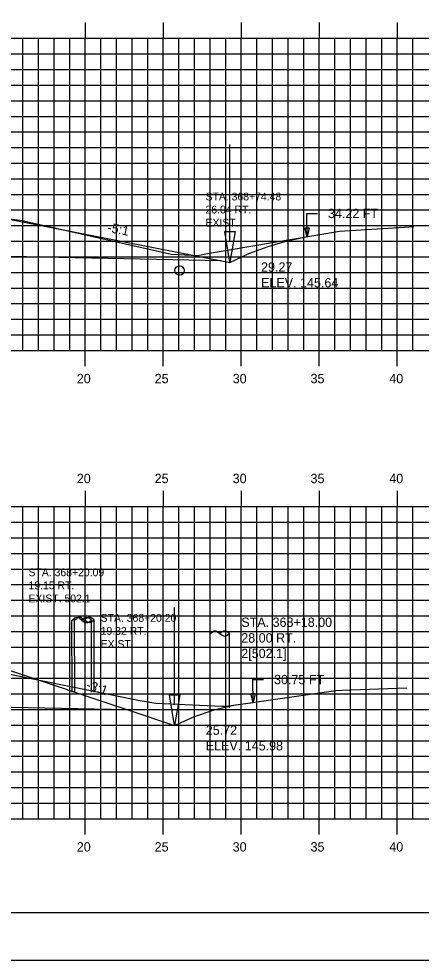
# Model space of a CAD drawing. Extents: x 1147855 to 1148025, y 608981 to 609091.
# Drawn here: x 1147953.9 to 1147979.7, y 608981.3 to 609041.6 of the extents above; entities that cross this region are included whole.
import ezdxf

# ---------------------------------------------------------------- set-up
doc = ezdxf.new("R2010")
doc.units = 0
for name, color, linetype in [('ANNOTATION', 7, 'Continuous'), ('BORDER', 7, 'Continuous'), ('D_Drainage_Ditch_Line', 7, 'Continuous'), ('D_Roadway_SlopeLines', 7, 'Continuous'), ('D_Roadway_SubGrade', 7, 'Continuous'), ('D_Text_Monospaced', 7, 'Continuous'), ('D_Text_Standard', 7, 'Continuous'), ('D_Utilities_Pole_Joint_Rt', 7, 'Continuous'), ('H_V ANNOTATION', 7, 'Continuous'), ('MAJOR', 7, 'Continuous'), ('MINOR', 7, 'Continuous'), ('PLOT BOUNDARY', 7, 'Continuous'), ('S_Drainage_Invert', 7, 'Continuous'), ('S_Roadway_Centerline', 7, 'Continuous'), ('S_Utilities_Pole_Power', 7, 'Continuous')]:
    doc.layers.add(name, color=color, linetype=linetype)

msp = doc.modelspace()

# ---------------------------------------------------------------- linework, layer by layer
for points in [[(1147923.21, 609028.779), (1147923.211, 609028.779), (1147927.211, 609028.939), (1147938.211, 609029.159), (1147949.211, 609028.939), (1147953.211, 609028.779), (1147966.938, 609026.085), (1147967.48, 609025.978), (1147968.704, 609026.54), (1147969.928, 609026.999), (1147971.152, 609027.357), (1147972.377, 609027.613)], [(1147922.727, 608999.809), (1147923.21, 608999.889), (1147923.211, 608999.889), (1147927.211, 609000.049), (1147938.211, 609000.269), (1147949.211, 609000.049), (1147953.211, 608999.889), (1147960.934, 608997.315), (1147963.934, 608996.315), (1147963.962, 608996.329), (1147965.212, 608996.889), (1147966.462, 608997.318), (1147967.712, 608997.616), (1147968.962, 608997.784)]]:
    msp.add_lwpolyline(points)
at = {"layer": 'BORDER'}
msp.add_lwpolyline([(1147863.211, 608984.335), (1148023.211, 608984.335), (1148023.211, 609089.335), (1147863.211, 609089.335)], close=True, dxfattribs=at)
at = {"layer": 'D_Drainage_Ditch_Line'}
for p, q in [((1147967.48, 609027.291), (1147967.48, 609033.534)), ((1147963.934, 608997.627), (1147963.934, 609003.871))]:
    msp.add_line(p, q, dxfattribs=at)
for points in [[(1147967.151, 609027.947), (1147967.808, 609027.947), (1147967.48, 609025.978)], [(1147963.606, 608998.283), (1147964.262, 608998.283), (1147963.934, 608996.315)]]:
    msp.add_lwpolyline(points, close=True, dxfattribs=at)
at = {"layer": 'D_Roadway_SlopeLines'}
for points in [[(1147967.48, 609025.978), (1147968.704, 609026.54), (1147969.928, 609026.999), (1147971.152, 609027.357), (1147972.377, 609027.613)], [(1147966.938, 609026.085), (1147967.48, 609025.978)], [(1147963.934, 608996.315), (1147963.962, 608996.329), (1147965.212, 608996.889), (1147966.462, 608997.318), (1147967.712, 608997.616), (1147968.962, 608997.784)], [(1147960.934, 608997.315), (1147963.934, 608996.315)]]:
    msp.add_lwpolyline(points, dxfattribs=at)
at = {"layer": 'D_Roadway_SubGrade'}
for points in [[(1147949.211, 609028.523), (1147949.211, 609028.689), (1147953.211, 609028.529), (1147953.211, 609028.779), (1147953.211, 609028.779), (1147966.938, 609026.085), (1147949.211, 609026.439)], [(1147949.211, 608999.633), (1147949.211, 608999.799), (1147953.211, 608999.639), (1147953.211, 608999.889), (1147953.211, 608999.889), (1147960.934, 608997.315), (1147949.211, 608997.549)]]:
    msp.add_lwpolyline(points, close=True, dxfattribs=at)
at = {"layer": 'D_Text_Standard'}
for points in [[(1147972.428, 609027.613), (1147972.408, 609029.117), (1147973.088, 609029.117)], [(1147968.962, 608997.784), (1147968.951, 608999.255), (1147969.631, 608999.255)]]:
    msp.add_lwpolyline(points, dxfattribs=at)
for points in [[(1147972.428, 609027.613), (1147972.275, 609028.193), (1147972.566, 609028.197)], [(1147968.962, 608997.784), (1147968.812, 608998.365), (1147969.103, 608998.367)]]:
    msp.add_lwpolyline(points, close=True, dxfattribs=at)
at = {"layer": 'D_Utilities_Pole_Joint_Rt'}
for p, q in [((1147966.211, 609002.199), (1147966.367, 609002.31)), ((1147966.211, 608997.442), (1147966.211, 609002.199)), ((1147966.679, 609002.31), (1147966.835, 609002.199)), ((1147966.991, 609002.31), (1147966.835, 609002.199)), ((1147966.835, 609002.199), (1147966.991, 609002.089)), ((1147967.461, 609002.199), (1147967.304, 609002.31)), ((1147967.304, 609002.089), (1147967.461, 609002.199)), ((1147967.461, 608997.442), (1147967.461, 609002.199))]:
    msp.add_line(p, q, dxfattribs=at)
for centre, start, end in [((1147966.523, 609002.089), 90, 125.26439), ((1147966.523, 609002.089), 54.73561, 90), ((1147967.148, 609002.089), 90, 125.26439), ((1147967.148, 609002.31), 234.73561, 270), ((1147967.148, 609002.089), 54.73561, 90), ((1147967.148, 609002.31), 270, 305.26439)]:
    msp.add_arc(centre, 0.271, start, end, dxfattribs=at)
at = {"layer": 'MAJOR'}
for p, q in [((1147958.211, 609041.337), (1147958.211, 609040.335)), ((1147963.211, 609041.337), (1147963.211, 609040.335)), ((1147968.211, 609041.337), (1147968.211, 609040.335)), ((1147973.211, 609041.337), (1147973.211, 609040.335)), ((1147978.211, 609041.337), (1147978.211, 609040.335)), ((1147868.211, 609040.335), (1148008.211, 609040.335)), ((1147868.211, 609040.335), (1148008.211, 609040.335)), ((1147958.211, 609020.335), (1147958.211, 609040.335)), ((1147963.211, 609020.335), (1147963.211, 609040.335)), ((1147968.211, 609020.335), (1147968.211, 609040.335)), ((1147973.211, 609020.335), (1147973.211, 609040.335)), ((1147978.211, 609020.335), (1147978.211, 609040.335)), ((1147868.211, 609035.335), (1148008.211, 609035.335)), ((1147868.211, 609030.335), (1148008.211, 609030.335)), ((1147868.211, 609025.335), (1148008.211, 609025.335)), ((1147868.211, 609020.335), (1148008.211, 609020.335)), ((1147868.211, 609020.335), (1148008.211, 609020.335)), ((1147958.211, 609019.333), (1147958.211, 609020.335)), ((1147963.211, 609019.333), (1147963.211, 609020.335)), ((1147968.211, 609019.333), (1147968.211, 609020.335)), ((1147973.211, 609019.333), (1147973.211, 609020.335)), ((1147978.211, 609019.333), (1147978.211, 609020.335)), ((1147958.211, 609011.337), (1147958.211, 609010.335)), ((1147963.211, 609011.337), (1147963.211, 609010.335)), ((1147968.211, 609011.337), (1147968.211, 609010.335)), ((1147973.211, 609011.337), (1147973.211, 609010.335)), ((1147978.211, 609011.337), (1147978.211, 609010.335)), ((1147868.211, 609010.335), (1148008.211, 609010.335)), ((1147868.211, 609010.335), (1148008.211, 609010.335)), ((1147958.211, 608990.335), (1147958.211, 609010.335)), ((1147963.211, 608990.335), (1147963.211, 609010.335)), ((1147968.211, 608990.335), (1147968.211, 609010.335)), ((1147973.211, 608990.335), (1147973.211, 609010.335)), ((1147978.211, 608990.335), (1147978.211, 609010.335)), ((1147868.211, 609005.335), (1148008.211, 609005.335)), ((1147868.211, 609000.335), (1148008.211, 609000.335)), ((1147868.211, 608995.335), (1148008.211, 608995.335)), ((1147868.211, 608990.335), (1148008.211, 608990.335)), ((1147868.211, 608990.335), (1148008.211, 608990.335)), ((1147958.211, 608989.333), (1147958.211, 608990.335)), ((1147963.211, 608989.333), (1147963.211, 608990.335)), ((1147968.211, 608989.333), (1147968.211, 608990.335)), ((1147973.211, 608989.333), (1147973.211, 608990.335)), ((1147978.211, 608989.333), (1147978.211, 608990.335))]:
    msp.add_line(p, q, dxfattribs=at)
at = {"layer": 'MINOR'}
for p, q in [((1147954.211, 609020.335), (1147954.211, 609040.335)), ((1147955.211, 609020.335), (1147955.211, 609040.335)), ((1147956.211, 609020.335), (1147956.211, 609040.335)), ((1147957.211, 609020.335), (1147957.211, 609040.335)), ((1147959.211, 609020.335), (1147959.211, 609040.335)), ((1147960.211, 609020.335), (1147960.211, 609040.335)), ((1147961.211, 609020.335), (1147961.211, 609040.335)), ((1147962.211, 609020.335), (1147962.211, 609040.335)), ((1147964.211, 609020.335), (1147964.211, 609040.335)), ((1147965.211, 609020.335), (1147965.211, 609040.335)), ((1147966.211, 609020.335), (1147966.211, 609040.335)), ((1147967.211, 609020.335), (1147967.211, 609040.335)), ((1147969.211, 609020.335), (1147969.211, 609040.335)), ((1147970.211, 609020.335), (1147970.211, 609040.335)), ((1147971.211, 609020.335), (1147971.211, 609040.335)), ((1147972.211, 609020.335), (1147972.211, 609040.335)), ((1147974.211, 609020.335), (1147974.211, 609040.335)), ((1147975.211, 609020.335), (1147975.211, 609040.335)), ((1147976.211, 609020.335), (1147976.211, 609040.335)), ((1147977.211, 609020.335), (1147977.211, 609040.335)), ((1147979.211, 609020.335), (1147979.211, 609040.335)), ((1147868.211, 609039.335), (1148008.211, 609039.335)), ((1147868.211, 609038.335), (1148008.211, 609038.335)), ((1147868.211, 609037.335), (1148008.211, 609037.335)), ((1147868.211, 609036.335), (1148008.211, 609036.335)), ((1147868.211, 609034.335), (1148008.211, 609034.335)), ((1147868.211, 609033.335), (1148008.211, 609033.335)), ((1147868.211, 609032.335), (1148008.211, 609032.335)), ((1147868.211, 609031.335), (1148008.211, 609031.335)), ((1147868.211, 609029.335), (1148008.211, 609029.335)), ((1147868.211, 609028.335), (1148008.211, 609028.335)), ((1147868.211, 609027.335), (1148008.211, 609027.335)), ((1147868.211, 609026.335), (1148008.211, 609026.335)), ((1147868.211, 609024.335), (1148008.211, 609024.335)), ((1147868.211, 609023.335), (1148008.211, 609023.335)), ((1147868.211, 609022.335), (1148008.211, 609022.335)), ((1147868.211, 609021.335), (1148008.211, 609021.335)), ((1147954.211, 608990.335), (1147954.211, 609010.335)), ((1147955.211, 608990.335), (1147955.211, 609010.335)), ((1147956.211, 608990.335), (1147956.211, 609010.335)), ((1147957.211, 608990.335), (1147957.211, 609010.335)), ((1147959.211, 608990.335), (1147959.211, 609010.335)), ((1147960.211, 608990.335), (1147960.211, 609010.335)), ((1147961.211, 608990.335), (1147961.211, 609010.335)), ((1147962.211, 608990.335), (1147962.211, 609010.335)), ((1147964.211, 608990.335), (1147964.211, 609010.335)), ((1147965.211, 608990.335), (1147965.211, 609010.335)), ((1147966.211, 608990.335), (1147966.211, 609010.335)), ((1147967.211, 608990.335), (1147967.211, 609010.335)), ((1147969.211, 608990.335), (1147969.211, 609010.335)), ((1147970.211, 608990.335), (1147970.211, 609010.335)), ((1147971.211, 608990.335), (1147971.211, 609010.335)), ((1147972.211, 608990.335), (1147972.211, 609010.335)), ((1147974.211, 608990.335), (1147974.211, 609010.335)), ((1147975.211, 608990.335), (1147975.211, 609010.335)), ((1147976.211, 608990.335), (1147976.211, 609010.335)), ((1147977.211, 608990.335), (1147977.211, 609010.335)), ((1147979.211, 608990.335), (1147979.211, 609010.335)), ((1147868.211, 609009.335), (1148008.211, 609009.335)), ((1147868.211, 609008.335), (1148008.211, 609008.335)), ((1147868.211, 609007.335), (1148008.211, 609007.335)), ((1147868.211, 609006.335), (1148008.211, 609006.335)), ((1147868.211, 609004.335), (1148008.211, 609004.335)), ((1147868.211, 609003.335), (1148008.211, 609003.335)), ((1147868.211, 609002.335), (1148008.211, 609002.335)), ((1147868.211, 609001.335), (1148008.211, 609001.335)), ((1147868.211, 608999.335), (1148008.211, 608999.335)), ((1147868.211, 608998.335), (1148008.211, 608998.335)), ((1147868.211, 608997.335), (1148008.211, 608997.335)), ((1147868.211, 608996.335), (1148008.211, 608996.335)), ((1147868.211, 608994.335), (1148008.211, 608994.335)), ((1147868.211, 608993.335), (1148008.211, 608993.335)), ((1147868.211, 608992.335), (1148008.211, 608992.335)), ((1147868.211, 608991.335), (1148008.211, 608991.335))]:
    msp.add_line(p, q, dxfattribs=at)
at = {"layer": 'PLOT BOUNDARY'}
msp.add_lwpolyline([(1147855.117, 608981.276), (1148025.117, 608981.276), (1148025.117, 609091.276), (1147855.117, 609091.276)], close=True, dxfattribs=at)
at = {"layer": 'S_Drainage_Invert'}
msp.add_circle((1147964.252, 609025.45), 0.3, dxfattribs=at)
at = {"layer": 'S_Roadway_Centerline'}
for points in [[(1147905.033, 609030.646), (1147917.167, 609029.936), (1147920.074, 609028.979), (1147920.713, 609028.933), (1147923.925, 609029.216), (1147924.199, 609029.231), (1147926.359, 609029.359), (1147926.651, 609029.377), (1147927.806, 609029.391), (1147938.591, 609029.489), (1147940.789, 609029.431), (1147952.444, 609028.899), (1147954.159, 609028.669), (1147954.197, 609028.662), (1147954.21, 609028.663), (1147954.245, 609028.651), (1147963.64, 609026.518), (1147963.717, 609026.515), (1147965.429, 609026.412), (1147966.055, 609026.554), (1147974.498, 609027.968), (1147978.677, 609028.23), (1147979.275, 609028.271)], [(1147903.402, 609000.314), (1147911.816, 609000.149), (1147915.16, 609000.018), (1147918.794, 608999.761), (1147922.073, 608999.773), (1147923.723, 608999.863), (1147925.309, 608999.916), (1147926.955, 609000.021), (1147933.547, 609000.1), (1147938.607, 609000.171), (1147945.257, 608999.995), (1147950.145, 608999.868), (1147951.153, 608999.855), (1147952.52, 608999.773), (1147961.597, 608997.939), (1147962.723, 608997.73), (1147966.96, 608997.559), (1147967.211, 608997.54), (1147967.577, 608997.583), (1147974.272, 608998.555), (1147974.652, 608998.571), (1147978.833, 608998.728)]]:
    msp.add_lwpolyline(points, dxfattribs=at)
at = {"layer": 'S_Utilities_Pole_Power'}
for p, q in [((1147957.36, 608998.446), (1147957.357, 609003.066)), ((1147957.36, 609003.066), (1147957.516, 609003.176)), ((1147957.529, 608998.456), (1147957.525, 609003.075)), ((1147957.529, 609003.075), (1147957.685, 609003.186)), ((1147957.829, 609003.176), (1147957.985, 609003.066)), ((1147958.142, 609003.176), (1147957.985, 609003.066)), ((1147957.985, 609003.066), (1147958.142, 609002.955)), ((1147957.997, 609003.186), (1147958.153, 609003.075)), ((1147958.31, 609003.186), (1147958.153, 609003.075)), ((1147958.153, 609003.075), (1147958.31, 609002.965)), ((1147958.61, 609003.066), (1147958.454, 609003.176)), ((1147958.454, 609002.955), (1147958.61, 609003.066)), ((1147958.61, 608998.446), (1147958.607, 609003.066)), ((1147958.779, 609003.075), (1147958.622, 609003.186)), ((1147958.622, 609002.965), (1147958.779, 609003.075)), ((1147958.779, 608998.456), (1147958.775, 609003.075))]:
    msp.add_line(p, q, dxfattribs=at)
for centre, start, end in [((1147957.672, 609002.955), 90, 125.26439), ((1147957.672, 609002.955), 54.73561, 90), ((1147957.841, 609002.965), 90, 125.26439), ((1147957.841, 609002.965), 54.73561, 90), ((1147958.297, 609002.955), 90, 125.26439), ((1147958.297, 609002.955), 54.73561, 90), ((1147958.466, 609002.965), 90, 125.26439), ((1147958.466, 609002.965), 54.73561, 90), ((1147958.297, 609003.176), 234.73561, 270), ((1147958.297, 609003.176), 270, 305.26439), ((1147958.466, 609003.186), 234.73561, 270), ((1147958.466, 609003.186), 270, 305.26439)]:
    msp.add_arc(centre, 0.271, start, end, dxfattribs=at)

# ---------------------------------------------------------------- texts
at = {"layer": 'ANNOTATION'}
for s, rotation, p in [('-5:1', 348.895, (1147959.593, 609027.945)), ('-3:1', 341.56521, (1147958.222, 608998.673))]:
    msp.add_text(s, height=0.6, rotation=rotation, dxfattribs=at).set_placement(p)
at = {"layer": 'D_Text_Monospaced'}
for s, height, p in [('STA. 368+74.48', 0.49998, (1147965.919, 609029.948)), ('26.04 RT.', 0.5, (1147965.919, 609029.114)), ('EXIST. ', 0.5, (1147965.919, 609028.274)), ('STA. 368+20.09', 0.49998, (1147954.57, 609005.872)), ('19.15 RT.', 0.5, (1147954.57, 609005.038)), ('EXIST. 502.1', 0.49998, (1147954.57, 609004.198)), ('STA. 368+20.20', 0.49998, (1147959.195, 609002.954)), ('19.32 RT.', 0.5, (1147959.195, 609002.12)), ('EXIST. ', 0.5, (1147959.195, 609001.28))]:
    msp.add_text(s, height=height, dxfattribs=at).set_placement(p)
at = {"layer": 'D_Text_Standard'}
for s, p in [('34.22 FT', (1147973.768, 609028.817)), ('29.27', (1147969.48, 609025.378)), ('ELEV. 145.64', (1147969.48, 609024.376)), ('STA. 368+18.00', (1147968.211, 609002.625)), ('28.00 RT.', (1147968.211, 609001.623)), ('2[502.1] ', (1147968.211, 609000.627)), ('30.75 FT', (1147970.311, 608998.955)), ('25.72', (1147965.934, 608995.715)), ('ELEV. 145.98', (1147965.934, 608994.713))]:
    msp.add_text(s, height=0.6, dxfattribs=at).set_placement(p)
at = {"layer": 'H_V ANNOTATION'}
for s, p in [('20', (1147957.665, 609018.235)), ('25', (1147962.657, 609018.235)), ('30', (1147967.659, 609018.235)), ('35', (1147972.651, 609018.235)), ('40', (1147977.697, 609018.235)), ('20', (1147957.665, 609011.835)), ('25', (1147962.657, 609011.835)), ('30', (1147967.659, 609011.835)), ('35', (1147972.651, 609011.835)), ('40', (1147977.697, 609011.835)), ('20', (1147957.665, 608988.235)), ('25', (1147962.657, 608988.235)), ('30', (1147967.659, 608988.235)), ('35', (1147972.651, 608988.235)), ('40', (1147977.697, 608988.235))]:
    msp.add_text(s, height=0.6, dxfattribs=at).set_placement(p)

doc.saveas('drawing.dxf')
